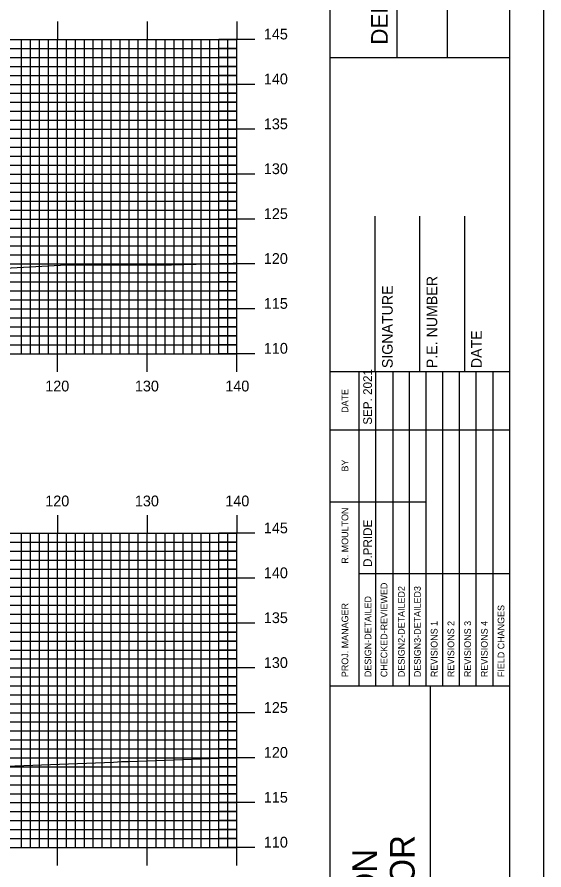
# Model space of a CAD drawing. Extents: x 1789337 to 1789680, y 442591 to 442811.
# Drawn here: x 1789618.2 to 1789676.9, y 442666.2 to 442761.2 of the extents above; entities that cross this region are included whole.
import ezdxf

# ---------------------------------------------------------------- set-up
doc = ezdxf.new("R2010")
doc.units = 0
for name, color, linetype in [('BORDER', 7, 'Continuous'), ('H_V ANNOTATION', 7, 'Continuous'), ('MAJOR', 7, 'Continuous'), ('MINOR', 7, 'Continuous'), ('PLOT BOUNDARY', 7, 'Continuous'), ('S_Roadway_Centerline', 7, 'Continuous')]:
    doc.layers.add(name, color=color, linetype=linetype)

msp = doc.modelspace()

# ---------------------------------------------------------------- linework, layer by layer
at = {"layer": 'BORDER'}
for p, q in [((1789653.07, 442596.665), (1789653.07, 442806.665)), ((1789660.527, 442756.659), (1789660.527, 442806.659)), ((1789666.117, 442756.659), (1789666.117, 442806.659)), ((1789653.071, 442756.653), (1789673.07, 442756.653)), ((1789658.07, 442721.671), (1789658.07, 442738.966)), ((1789663.07, 442721.671), (1789663.07, 442738.966)), ((1789668.07, 442721.671), (1789668.07, 442738.966)), ((1789653.07, 442721.671), (1789673.07, 442721.671)), ((1789653.07, 442686.671), (1789673.07, 442686.671)), ((1789664.252, 442616.671), (1789664.252, 442686.671))]:
    msp.add_line(p, q, dxfattribs=at)
msp.add_lwpolyline([(1789353.07, 442596.665), (1789673.07, 442596.665), (1789673.07, 442806.665), (1789353.07, 442806.665)], close=True, dxfattribs=at)
for points in [[(1789656.299, 442715.171), (1789656.299, 442721.671)], [(1789658.165, 442686.677), (1789658.165, 442721.671)], [(1789660.028, 442721.671), (1789660.028, 442686.677)], [(1789661.891, 442686.677), (1789661.891, 442721.671)], [(1789663.755, 442686.677), (1789663.755, 442721.671)], [(1789665.618, 442686.677), (1789665.618, 442721.671)], [(1789667.481, 442686.677), (1789667.481, 442721.671)], [(1789669.345, 442686.677), (1789669.345, 442721.671)], [(1789671.208, 442686.677), (1789671.208, 442721.671)], [(1789656.301, 442686.677), (1789656.301, 442720.259)], [(1789653.07, 442715.171), (1789673.07, 442715.171)], [(1789653.07, 442707.171), (1789656.301, 442707.171)], [(1789656.299, 442707.171), (1789663.753, 442707.171)], [(1789656.299, 442699.171), (1789673.07, 442699.171)]]:
    msp.add_lwpolyline(points, dxfattribs=at)
at = {"layer": 'MAJOR'}
for p, q in [((1789622.67, 442760.669), (1789622.67, 442758.665)), ((1789632.67, 442760.669), (1789632.67, 442758.665)), ((1789642.67, 442760.669), (1789642.67, 442758.665)), ((1789362.67, 442758.665), (1789642.67, 442758.665)), ((1789362.67, 442758.665), (1789642.67, 442758.665)), ((1789622.67, 442723.665), (1789622.67, 442758.665)), ((1789632.67, 442723.665), (1789632.67, 442758.665)), ((1789644.674, 442758.665), (1789640.666, 442758.665)), ((1789642.67, 442723.665), (1789642.67, 442758.665)), ((1789642.67, 442723.665), (1789642.67, 442758.665)), ((1789362.67, 442753.665), (1789642.67, 442753.665)), ((1789644.674, 442753.665), (1789640.666, 442753.665)), ((1789362.67, 442748.665), (1789642.67, 442748.665)), ((1789644.674, 442748.665), (1789640.666, 442748.665)), ((1789362.67, 442743.665), (1789642.67, 442743.665)), ((1789644.674, 442743.665), (1789640.666, 442743.665)), ((1789362.67, 442738.665), (1789642.67, 442738.665)), ((1789644.674, 442738.665), (1789640.666, 442738.665)), ((1789362.67, 442733.665), (1789642.67, 442733.665)), ((1789644.674, 442733.665), (1789640.666, 442733.665)), ((1789362.67, 442728.665), (1789642.67, 442728.665)), ((1789644.674, 442728.665), (1789640.666, 442728.665)), ((1789362.67, 442723.665), (1789642.67, 442723.665)), ((1789362.67, 442723.665), (1789642.67, 442723.665)), ((1789622.67, 442721.661), (1789622.67, 442723.665)), ((1789632.67, 442721.661), (1789632.67, 442723.665)), ((1789644.674, 442723.665), (1789640.666, 442723.665)), ((1789642.67, 442721.661), (1789642.67, 442723.665)), ((1789622.67, 442705.669), (1789622.67, 442703.665)), ((1789632.67, 442705.669), (1789632.67, 442703.665)), ((1789642.67, 442705.669), (1789642.67, 442703.665)), ((1789362.67, 442703.665), (1789642.67, 442703.665)), ((1789362.67, 442703.665), (1789642.67, 442703.665)), ((1789622.67, 442668.665), (1789622.67, 442703.665)), ((1789632.67, 442668.665), (1789632.67, 442703.665)), ((1789644.674, 442703.665), (1789640.666, 442703.665)), ((1789642.67, 442668.665), (1789642.67, 442703.665)), ((1789642.67, 442668.665), (1789642.67, 442703.665)), ((1789362.67, 442698.665), (1789642.67, 442698.665)), ((1789644.674, 442698.665), (1789640.666, 442698.665)), ((1789362.67, 442693.665), (1789642.67, 442693.665)), ((1789644.674, 442693.665), (1789640.666, 442693.665)), ((1789362.67, 442688.665), (1789642.67, 442688.665)), ((1789644.674, 442688.665), (1789640.666, 442688.665)), ((1789362.67, 442683.665), (1789642.67, 442683.665)), ((1789644.674, 442683.665), (1789640.666, 442683.665)), ((1789362.67, 442678.665), (1789642.67, 442678.665)), ((1789644.674, 442678.665), (1789640.666, 442678.665)), ((1789362.67, 442673.665), (1789642.67, 442673.665)), ((1789644.674, 442673.665), (1789640.666, 442673.665)), ((1789362.67, 442668.665), (1789642.67, 442668.665)), ((1789362.67, 442668.665), (1789642.67, 442668.665)), ((1789622.67, 442666.661), (1789622.67, 442668.665)), ((1789632.67, 442666.661), (1789632.67, 442668.665)), ((1789644.674, 442668.665), (1789640.666, 442668.665)), ((1789642.67, 442666.661), (1789642.67, 442668.665))]:
    msp.add_line(p, q, dxfattribs=at)
at = {"layer": 'MINOR'}
for p, q in [((1789618.67, 442723.665), (1789618.67, 442758.665)), ((1789619.67, 442723.665), (1789619.67, 442758.665)), ((1789620.67, 442723.665), (1789620.67, 442758.665)), ((1789621.67, 442723.665), (1789621.67, 442758.665)), ((1789623.67, 442723.665), (1789623.67, 442758.665)), ((1789624.67, 442723.665), (1789624.67, 442758.665)), ((1789625.67, 442723.665), (1789625.67, 442758.665)), ((1789626.67, 442723.665), (1789626.67, 442758.665)), ((1789627.67, 442723.665), (1789627.67, 442758.665)), ((1789628.67, 442723.665), (1789628.67, 442758.665)), ((1789629.67, 442723.665), (1789629.67, 442758.665)), ((1789630.67, 442723.665), (1789630.67, 442758.665)), ((1789631.67, 442723.665), (1789631.67, 442758.665)), ((1789633.67, 442723.665), (1789633.67, 442758.665)), ((1789634.67, 442723.665), (1789634.67, 442758.665)), ((1789635.67, 442723.665), (1789635.67, 442758.665)), ((1789636.67, 442723.665), (1789636.67, 442758.665)), ((1789637.67, 442723.665), (1789637.67, 442758.665)), ((1789638.67, 442723.665), (1789638.67, 442758.665)), ((1789639.67, 442723.665), (1789639.67, 442758.665)), ((1789640.67, 442723.665), (1789640.67, 442758.665)), ((1789641.67, 442723.665), (1789641.67, 442758.665)), ((1789362.67, 442757.665), (1789642.67, 442757.665)), ((1789642.67, 442757.665), (1789640.666, 442757.665)), ((1789362.67, 442756.665), (1789642.67, 442756.665)), ((1789642.67, 442756.665), (1789640.666, 442756.665)), ((1789362.67, 442755.665), (1789642.67, 442755.665)), ((1789642.67, 442755.665), (1789640.666, 442755.665)), ((1789362.67, 442754.665), (1789642.67, 442754.665)), ((1789642.67, 442754.665), (1789640.666, 442754.665)), ((1789362.67, 442752.665), (1789642.67, 442752.665)), ((1789642.67, 442752.665), (1789640.666, 442752.665)), ((1789362.67, 442751.665), (1789642.67, 442751.665)), ((1789642.67, 442751.665), (1789640.666, 442751.665)), ((1789362.67, 442750.665), (1789642.67, 442750.665)), ((1789642.67, 442750.665), (1789640.666, 442750.665)), ((1789362.67, 442749.665), (1789642.67, 442749.665)), ((1789642.67, 442749.665), (1789640.666, 442749.665)), ((1789362.67, 442747.665), (1789642.67, 442747.665)), ((1789642.67, 442747.665), (1789640.666, 442747.665)), ((1789362.67, 442746.665), (1789642.67, 442746.665)), ((1789642.67, 442746.665), (1789640.666, 442746.665)), ((1789362.67, 442745.665), (1789642.67, 442745.665)), ((1789642.67, 442745.665), (1789640.666, 442745.665)), ((1789362.67, 442744.665), (1789642.67, 442744.665)), ((1789642.67, 442744.665), (1789640.666, 442744.665)), ((1789362.67, 442742.665), (1789642.67, 442742.665)), ((1789642.67, 442742.665), (1789640.666, 442742.665)), ((1789362.67, 442741.665), (1789642.67, 442741.665)), ((1789642.67, 442741.665), (1789640.666, 442741.665)), ((1789362.67, 442740.665), (1789642.67, 442740.665)), ((1789642.67, 442740.665), (1789640.666, 442740.665)), ((1789362.67, 442739.665), (1789642.67, 442739.665)), ((1789642.67, 442739.665), (1789640.666, 442739.665)), ((1789362.67, 442737.665), (1789642.67, 442737.665)), ((1789642.67, 442737.665), (1789640.666, 442737.665)), ((1789362.67, 442736.665), (1789642.67, 442736.665)), ((1789642.67, 442736.665), (1789640.666, 442736.665)), ((1789362.67, 442735.665), (1789642.67, 442735.665)), ((1789642.67, 442735.665), (1789640.666, 442735.665)), ((1789362.67, 442734.665), (1789642.67, 442734.665)), ((1789642.67, 442734.665), (1789640.666, 442734.665)), ((1789362.67, 442732.665), (1789642.67, 442732.665)), ((1789642.67, 442732.665), (1789640.666, 442732.665)), ((1789362.67, 442731.665), (1789642.67, 442731.665)), ((1789642.67, 442731.665), (1789640.666, 442731.665)), ((1789362.67, 442730.665), (1789642.67, 442730.665)), ((1789642.67, 442730.665), (1789640.666, 442730.665)), ((1789362.67, 442729.665), (1789642.67, 442729.665)), ((1789642.67, 442729.665), (1789640.666, 442729.665)), ((1789362.67, 442727.665), (1789642.67, 442727.665)), ((1789642.67, 442727.665), (1789640.666, 442727.665)), ((1789362.67, 442726.665), (1789642.67, 442726.665)), ((1789642.67, 442726.665), (1789640.666, 442726.665)), ((1789362.67, 442725.665), (1789642.67, 442725.665)), ((1789642.67, 442725.665), (1789640.666, 442725.665)), ((1789362.67, 442724.665), (1789642.67, 442724.665)), ((1789642.67, 442724.665), (1789640.666, 442724.665)), ((1789618.67, 442668.665), (1789618.67, 442703.665)), ((1789619.67, 442668.665), (1789619.67, 442703.665)), ((1789620.67, 442668.665), (1789620.67, 442703.665)), ((1789621.67, 442668.665), (1789621.67, 442703.665)), ((1789623.67, 442668.665), (1789623.67, 442703.665)), ((1789624.67, 442668.665), (1789624.67, 442703.665)), ((1789625.67, 442668.665), (1789625.67, 442703.665)), ((1789626.67, 442668.665), (1789626.67, 442703.665)), ((1789627.67, 442668.665), (1789627.67, 442703.665)), ((1789628.67, 442668.665), (1789628.67, 442703.665)), ((1789629.67, 442668.665), (1789629.67, 442703.665)), ((1789630.67, 442668.665), (1789630.67, 442703.665)), ((1789631.67, 442668.665), (1789631.67, 442703.665)), ((1789633.67, 442668.665), (1789633.67, 442703.665)), ((1789634.67, 442668.665), (1789634.67, 442703.665)), ((1789635.67, 442668.665), (1789635.67, 442703.665)), ((1789636.67, 442668.665), (1789636.67, 442703.665)), ((1789637.67, 442668.665), (1789637.67, 442703.665)), ((1789638.67, 442668.665), (1789638.67, 442703.665)), ((1789639.67, 442668.665), (1789639.67, 442703.665)), ((1789640.67, 442668.665), (1789640.67, 442703.665)), ((1789641.67, 442668.665), (1789641.67, 442703.665)), ((1789362.67, 442702.665), (1789642.67, 442702.665)), ((1789642.67, 442702.665), (1789640.666, 442702.665)), ((1789362.67, 442701.665), (1789642.67, 442701.665)), ((1789642.67, 442701.665), (1789640.666, 442701.665)), ((1789362.67, 442700.665), (1789642.67, 442700.665)), ((1789642.67, 442700.665), (1789640.666, 442700.665)), ((1789362.67, 442699.665), (1789642.67, 442699.665)), ((1789642.67, 442699.665), (1789640.666, 442699.665)), ((1789362.67, 442697.665), (1789642.67, 442697.665)), ((1789642.67, 442697.665), (1789640.666, 442697.665)), ((1789362.67, 442696.665), (1789642.67, 442696.665)), ((1789642.67, 442696.665), (1789640.666, 442696.665)), ((1789362.67, 442695.665), (1789642.67, 442695.665)), ((1789642.67, 442695.665), (1789640.666, 442695.665)), ((1789362.67, 442694.665), (1789642.67, 442694.665)), ((1789642.67, 442694.665), (1789640.666, 442694.665)), ((1789362.67, 442692.665), (1789642.67, 442692.665)), ((1789642.67, 442692.665), (1789640.666, 442692.665)), ((1789362.67, 442691.665), (1789642.67, 442691.665)), ((1789642.67, 442691.665), (1789640.666, 442691.665)), ((1789362.67, 442690.665), (1789642.67, 442690.665)), ((1789642.67, 442690.665), (1789640.666, 442690.665)), ((1789362.67, 442689.665), (1789642.67, 442689.665)), ((1789642.67, 442689.665), (1789640.666, 442689.665)), ((1789362.67, 442687.665), (1789642.67, 442687.665)), ((1789642.67, 442687.665), (1789640.666, 442687.665)), ((1789362.67, 442686.665), (1789642.67, 442686.665)), ((1789642.67, 442686.665), (1789640.666, 442686.665)), ((1789362.67, 442685.665), (1789642.67, 442685.665)), ((1789642.67, 442685.665), (1789640.666, 442685.665)), ((1789362.67, 442684.665), (1789642.67, 442684.665)), ((1789642.67, 442684.665), (1789640.666, 442684.665)), ((1789362.67, 442682.665), (1789642.67, 442682.665)), ((1789642.67, 442682.665), (1789640.666, 442682.665)), ((1789362.67, 442681.665), (1789642.67, 442681.665)), ((1789642.67, 442681.665), (1789640.666, 442681.665)), ((1789362.67, 442680.665), (1789642.67, 442680.665)), ((1789642.67, 442680.665), (1789640.666, 442680.665)), ((1789362.67, 442679.665), (1789642.67, 442679.665)), ((1789642.67, 442679.665), (1789640.666, 442679.665)), ((1789362.67, 442677.665), (1789642.67, 442677.665)), ((1789642.67, 442677.665), (1789640.666, 442677.665)), ((1789362.67, 442676.665), (1789642.67, 442676.665)), ((1789642.67, 442676.665), (1789640.666, 442676.665)), ((1789362.67, 442675.665), (1789642.67, 442675.665)), ((1789642.67, 442675.665), (1789640.666, 442675.665)), ((1789362.67, 442674.665), (1789642.67, 442674.665)), ((1789642.67, 442674.665), (1789640.666, 442674.665)), ((1789362.67, 442672.665), (1789642.67, 442672.665)), ((1789642.67, 442672.665), (1789640.666, 442672.665)), ((1789362.67, 442671.665), (1789642.67, 442671.665)), ((1789642.67, 442671.665), (1789640.666, 442671.665)), ((1789362.67, 442670.665), (1789642.67, 442670.665)), ((1789642.67, 442670.665), (1789640.666, 442670.665)), ((1789362.67, 442669.665), (1789642.67, 442669.665)), ((1789642.67, 442669.665), (1789640.666, 442669.665))]:
    msp.add_line(p, q, dxfattribs=at)
at = {"layer": 'PLOT BOUNDARY'}
msp.add_lwpolyline([(1789336.883, 442590.547), (1789676.883, 442590.547), (1789676.883, 442810.547), (1789336.883, 442810.547)], close=True, dxfattribs=at)
at = {"layer": 'S_Roadway_Centerline'}
for points in [[(1789555.864, 442731.873), (1789568.605, 442731.978), (1789573.806, 442732.043), (1789587.913, 442732.4), (1789598.568, 442732.636), (1789613.336, 442733.012), (1789623.684, 442733.561), (1789635.39, 442733.548), (1789642.237, 442733.756), (1789642.67, 442733.78)], [(1789556.809, 442676.443), (1789575.02, 442676.753), (1789580.206, 442676.802), (1789590.842, 442677.48), (1789592.389, 442677.598), (1789593.11, 442677.575), (1789595.002, 442677.586), (1789611.872, 442677.544), (1789628.922, 442678.192), (1789629.792, 442678.252), (1789630.682, 442678.254), (1789642.67, 442678.712)]]:
    msp.add_lwpolyline(points, dxfattribs=at)

# ---------------------------------------------------------------- texts
at = {"layer": 'BORDER'}
for s, height, p in [('DEPARTMENT OF TRANSPORTATION', 1.86351, (1789659.483, 442758.077)), ('P.E. NUMBER', 1.1811, (1789664.991, 442722.055)), ('SIGNATURE', 1.1811, (1789660.03, 442722.055)), ('DATE', 1.1811, (1789669.952, 442722.055)), ('SEP. 2021', 0.9691, (1789657.716, 442715.762)), ('DATE', 0.7428, (1789655.078, 442717.083)), ('BY', 0.7428, (1789655.078, 442710.541)), ('R. MOULTON', 0.7455, (1789655.079, 442700.276)), ('D.PRIDE', 0.9691, (1789657.716, 442699.917)), ('CHECKED-REVIEWED', 0.7455, (1789659.432, 442687.647)), ('DESIGN2-DETAILED2', 0.7455, (1789661.369, 442687.647)), ('DESIGN3-DETAILED3', 0.7455, (1789663.158, 442687.647)), ('DESIGN-DETAILED', 0.7455, (1789657.643, 442687.647)), ('PROJ. MANAGER', 0.7455, (1789655.078, 442687.647)), ('FIELD CHANGES', 0.7455, (1789672.475, 442687.647)), ('REVISIONS 1', 0.7455, (1789665.022, 442687.647)), ('REVISIONS 2', 0.7455, (1789666.885, 442687.647)), ('REVISIONS 3', 0.7455, (1789668.748, 442687.647)), ('REVISIONS 4', 0.7455, (1789670.612, 442687.647)), ('1-395/ROUTE 9 CONNECTOR', 2.75575, (1789662.473, 442618.865)), ('BREWER TO EDDINGTON', 2.75575, (1789658.293, 442623.074))]:
    msp.add_text(s, height=height, rotation=90, dxfattribs=at).set_placement(p)
at = {"layer": 'H_V ANNOTATION'}
for s, p in [('145', (1789645.67, 442758.665)), ('140', (1789645.67, 442753.665)), ('135', (1789645.67, 442748.665)), ('130', (1789645.67, 442743.665)), ('125', (1789645.67, 442738.665)), ('120', (1789645.67, 442733.665)), ('115', (1789645.67, 442728.665)), ('110', (1789645.67, 442723.665)), ('120', (1789621.31, 442719.465)), ('130', (1789631.3, 442719.465)), ('140', (1789641.374, 442719.465)), ('120', (1789621.31, 442706.665)), ('130', (1789631.3, 442706.665)), ('140', (1789641.374, 442706.665)), ('145', (1789645.67, 442703.665)), ('140', (1789645.67, 442698.665)), ('135', (1789645.67, 442693.665)), ('130', (1789645.67, 442688.665)), ('125', (1789645.67, 442683.665)), ('120', (1789645.67, 442678.665)), ('115', (1789645.67, 442673.665)), ('110', (1789645.67, 442668.665))]:
    msp.add_text(s, height=1.2, dxfattribs=at).set_placement(p)

doc.saveas('drawing.dxf')
